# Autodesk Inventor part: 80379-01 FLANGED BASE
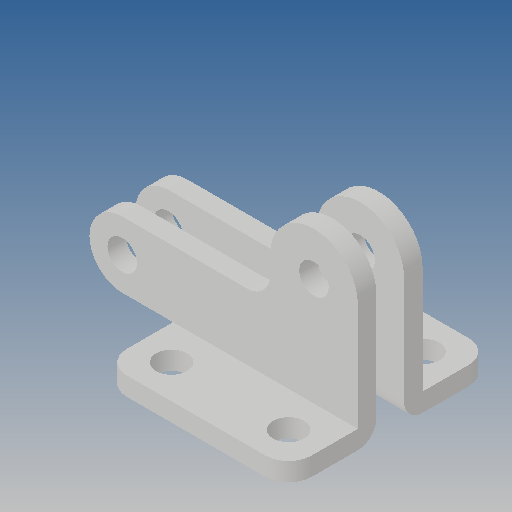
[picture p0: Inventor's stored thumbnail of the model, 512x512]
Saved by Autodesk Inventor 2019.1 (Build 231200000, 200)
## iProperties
Created: 2012-10
Part Number: 80379-01 FLANGED BASE
Material: Ogólny
Document SubType Name: Modeling
Designer: CADENGINEERING4
Density: 1 g/cm^3
Appearance: Domyślna
Author: CADENGINEERING4
Revision Number: ÈÎºÎ
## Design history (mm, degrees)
feature "Ô²½Ç1"
feature "¾µÏò1"
node "Bryła1"
node "Bryła2"
